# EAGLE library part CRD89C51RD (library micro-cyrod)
CRD89C51RD series 8 - bit single chip micro controller unit (MCU) with 64KB flash & 1K byte RAM embedded. Auto generated by make-symbol-device-package-bsdl.ulp Rev. 35 Source: CRD89C51RD_v001.pdf
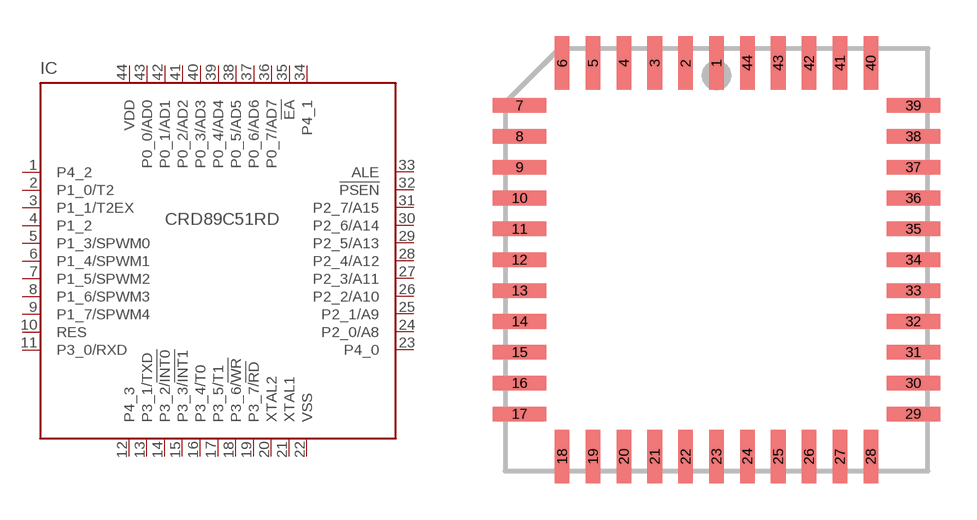
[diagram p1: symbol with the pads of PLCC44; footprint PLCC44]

Designator prefix IC

## CRD89C51RD (OC_FARNELL: unknown; OC_NEWARK: unknown)  [PLCC44]
1  P4_2
2  P1_0/T2
3  P1_1/T2EX
4  P1_2
5  P1_3/SPWM0
6  P1_4/SPWM1
7  P1_5/SPWM2
8  P1_6/SPWM3
9  P1_7/SPWM4
10  RES  in
11  P3_0/RXD
12  P4_3
13  P3_1/TXD
14  P3_2/!INT0
15  P3_3/!INT1
16  P3_4/T0
17  P3_5/T1
18  P3_6/!WR
19  P3_7/!RD
20  XTAL2  out
21  XTAL1  in
22  VSS  pwr
23  P4_0
24  P2_0/A8
25  P2_1/A9
26  P2_2/A10
27  P2_3/A11
28  P2_4/A12
29  P2_5/A13
30  P2_6/A14
31  P2_7/A15
32  !PSEN  out
33  ALE  out
34  P4_1
35  !EA  in
36  P0_7/AD7
37  P0_6/AD6
38  P0_5/AD5
39  P0_4/AD4
40  P0_3/AD3
41  P0_2/AD2
42  P0_1/AD1
43  P0_0/AD0
44  VDD  pwr

## Footprint PLCC44 (pad centres in mm)
PLASTIC LEADED CHIP CARRIER square
smd 0.6 x 2.2: 1 0,8.1; 2 -1.27,8.1; 3 -2.54,8.1; 4 -3.81,8.1; 5 -5.08,8.1; 6 -6.35,8.1; 18 -6.35,-8.1; 19 -5.08,-8.1; 20 -3.81,-8.1; 21 -2.54,-8.1; 22 -1.27,-8.1; 23 0,-8.1; 24 1.27,-8.1; 25 2.54,-8.1; 26 3.81,-8.1; 27 5.08,-8.1; 28 6.35,-8.1; 40 6.35,8.1; 41 5.08,8.1; 42 3.81,8.1; 43 2.54,8.1; 44 1.27,8.1
smd 2.2 x 0.6: 7 -8.1,6.35; 8 -8.1,5.08; 9 -8.1,3.81; 10 -8.1,2.54; 11 -8.1,1.27; 12 -8.1,0; 13 -8.1,-1.27; 14 -8.1,-2.54; 15 -8.1,-3.81; 16 -8.1,-5.08; 17 -8.1,-6.35; 29 8.1,-6.35; 30 8.1,-5.08; 31 8.1,-3.81; 32 8.1,-2.54; 33 8.1,-1.27; 34 8.1,0; 35 8.1,1.27; 36 8.1,2.54; 37 8.1,3.81; 38 8.1,5.08; 39 8.1,6.35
